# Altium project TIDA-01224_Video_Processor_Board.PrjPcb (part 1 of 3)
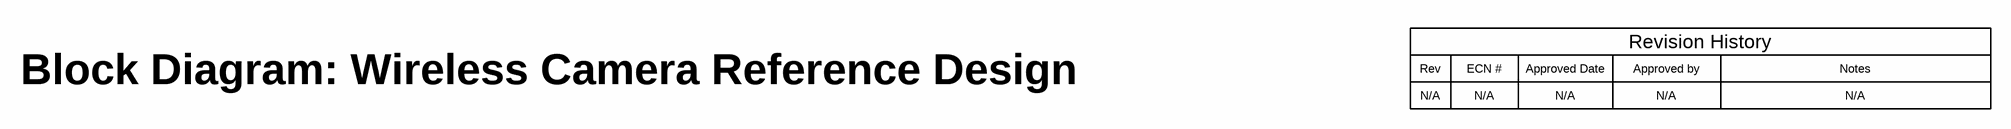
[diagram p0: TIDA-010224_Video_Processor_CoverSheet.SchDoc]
PRJ_Engineer: Sakshi Markhedkar; TID: TIDA-010224; TechSupport: http://www.ti.com/support; SCH_Rev: E1; PRJ_Title: Low-Power Wireless Camera Reference Design for Extended Battery Life; PRJ_Number: TIDA-010224; PRJ_Customer: Public Release; EVM_Orderable: N/A; Drawnby: Sakshi; CopyrightYear: 2018; Assembly Variant: 001
6 sheets, 509 parts. Net scope: global (net labels, ports and power ports of the same name join across sheets).
Board file: TIDA-010224_Video_Processor_PCB.PcbDoc
Sheets:
  TIDA-010224_Video_Processor_CoverSheet.SchDoc
  TIDA-010224_Video_Processor_Hardware.SchDoc
  TIDA-010224_Video_Processor_P01_Power_Delivery.SchDoc
  TIDA-010224_Video_Processor_P02_OA7000_Image_Sensor.SchDoc
  TIDA-010224_Video_Processor_P03_CC3235MODA_WIFI_Launchpad.SchDoc
  TIDA-010224_Video_Processor_P04_Peripherals.SchDoc

## Sheet TIDA-010224_Video_Processor_CoverSheet.SchDoc: TIDA-010224_Video_Processor_CoverSheet
size 431 x 279 mm; Date: Not shown in title block; ApprovedBy: Not shown in title block; CheckedBy: Not shown in title block; Author: Not shown in title block; CompanyName: Not shown in title block; DrawnBy: Sakshi Markhedkar; Engineer: Not shown in title block; Organization: Not shown in title block; Address1: Not shown in title block; Address2: Not shown in title block; Address3: Not shown in title block; Address4: Not shown in title block; DocumentNumber: 1; Revision: Use project parameter SCH_Rev; SheetNumber: 1; SheetTotal: 6; PageSetup: Record=PageOptions¦CenterHorizontal=True¦CenterVertical=True¦PrintScale=1.00¦XCorrection=1.00¦YCorrection=1.00¦PrintKind=0¦BorderSize=5000000¦LeftOffset=0¦BottomOffset=0¦Orientation=2¦PaperLength=1000¦PaperWidth=1000¦Scale=100¦PaperSource=15¦PrintQuality=600¦MediaType=1¦DitherType=10¦PaperKind=Letter¦PrintScaleMode=1

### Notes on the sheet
- Block Diagram: Wireless Camera Reference Design
- Rev
- N/A
- ECN #
- Approved Date
- Approved by
- Revision History
- Notes

## Sheet TIDA-010224_Video_Processor_Hardware.SchDoc: TIDA-010224_Hardware
size 431 x 279 mm; Date: Not shown in title block; ApprovedBy: Not shown in title block; CheckedBy: Not shown in title block; Author: Not shown in title block; CompanyName: Not shown in title block; DrawnBy: Sakshi Markhedkar; Engineer: Not shown in title block; Organization: Not shown in title block; Address1: Not shown in title block; Address2: Not shown in title block; Address3: Not shown in title block; Address4: Not shown in title block; DocumentNumber: 6; Revision: Use project parameter SCH_Rev; SheetNumber: 6; SheetTotal: 6; PageSetup: Record=PageOptions¦CenterHorizontal=True¦CenterVertical=True¦PrintScale=1.00¦XCorrection=1.00¦YCorrection=1.00¦PrintKind=0¦BorderSize=5000000¦LeftOffset=0¦BottomOffset=0¦Orientation=2¦PaperLength=1000¦PaperWidth=1000¦Scale=100¦PaperSource=15¦PrintQuality=600¦MediaType=1¦DitherType=10¦PaperKind=Letter¦PrintScaleMode=1
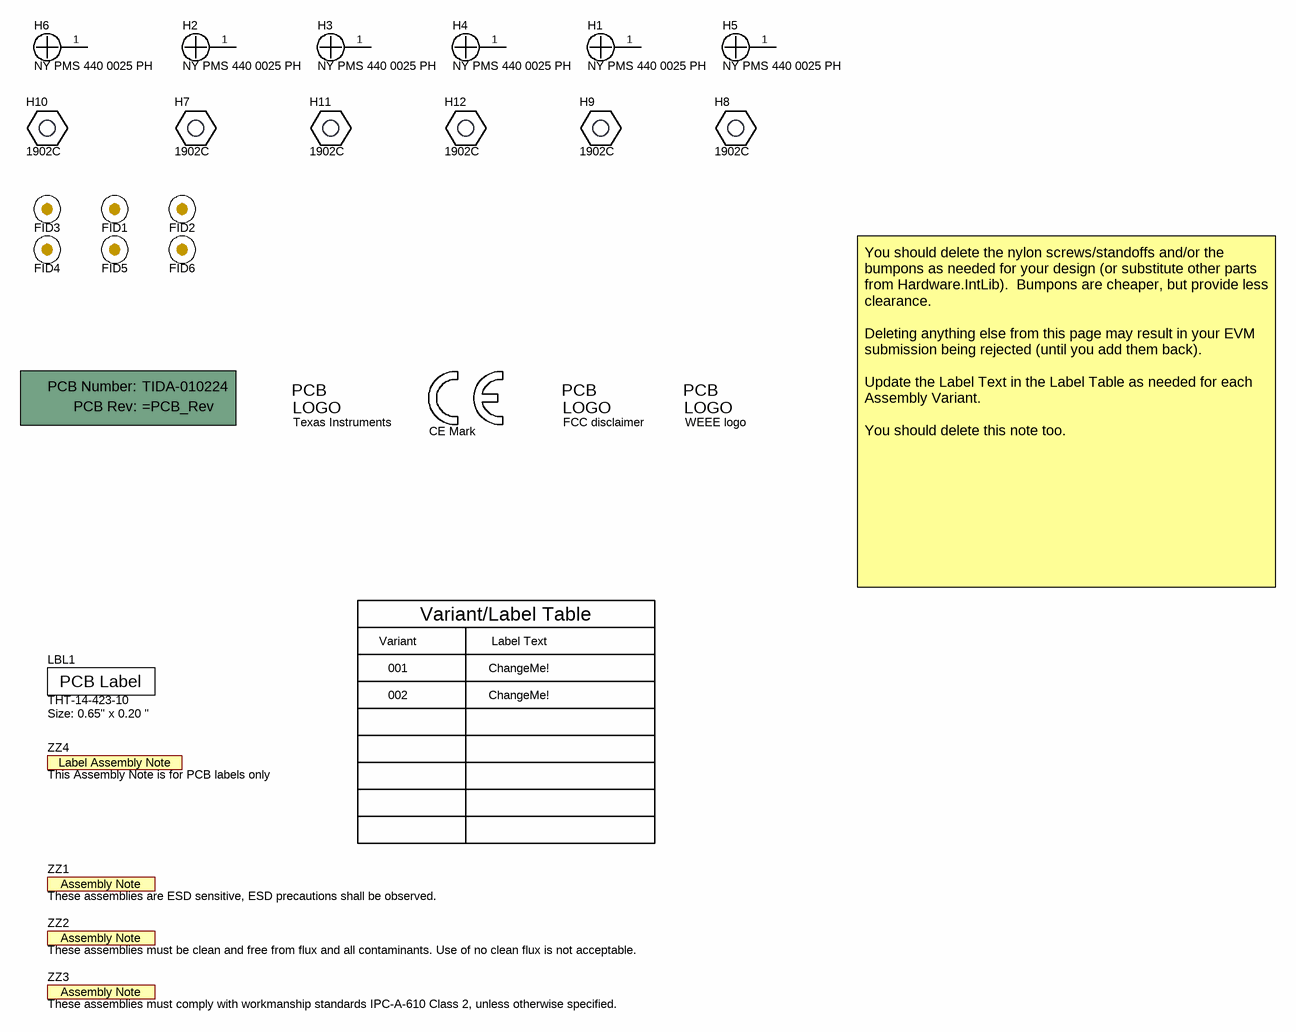
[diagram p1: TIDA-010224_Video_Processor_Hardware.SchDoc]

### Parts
!PCB1  Printed Circuit Board  (value not drawn)  (mechanical)
FID1  Fiducial  [Fiducial10-20]  (value not drawn)
FID2  Fiducial  [Fiducial10-20]  (value not drawn)
FID3  Fiducial  [Fiducial10-20]  (value not drawn)
FID4  Fiducial  [Fiducial10-20]  (value not drawn)
FID5  Fiducial  [Fiducial10-20]  (value not drawn)
FID6  Fiducial  [Fiducial10-20]  (value not drawn)
H1  NY PMS 440 0025 PH  [NY PMS 440 0025 PH]
H2  NY PMS 440 0025 PH  [NY PMS 440 0025 PH]
H3  NY PMS 440 0025 PH  [NY PMS 440 0025 PH]
H4  NY PMS 440 0025 PH  [NY PMS 440 0025 PH]
H5  NY PMS 440 0025 PH  [NY PMS 440 0025 PH]
H6  NY PMS 440 0025 PH  [NY PMS 440 0025 PH]
H7  1902C  [Keystone_1902C]
H8  1902C  [Keystone_1902C]
H9  1902C  [Keystone_1902C]
H10  1902C  [Keystone_1902C]
H11  1902C  [Keystone_1902C]
H12  1902C  [Keystone_1902C]
LBL1  THT-14-423-10  Note: Size: 0.65" x 0.20 "  [Label_650x200]
Logo1  FCC disclaimer  [FCC_disclaimer]  (no BOM)
Logo2  WEEE logo  [WEEE_Minimum]  (no BOM)
Logo3  Texas Instruments  [TI_Stacked_Overlay_Small]  (no BOM)
Logo4  CE Mark  [CE_Mark_5mm]  (no BOM)
ZZ1  These assemblies are ESD sensitive, ESD precautions shall be observed.  [AssemblyNote]  (no BOM)
ZZ2  These assemblies must be clean and free from flux and all contaminants. Use of no clean flux is not acceptable.  [AssemblyNote]  (no BOM)
ZZ3  These assemblies must comply with workmanship standards IPC-A-610 Class 2, unless otherwise specified.  [AssemblyNote]  (no BOM)
ZZ4  This Assembly Note is for PCB labels only  [AssemblyNoteLabel]  (no BOM)

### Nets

Not connected (* = marked no-connect by the designer): H1 1; H2 1; H3 1; H4 1; H5 1; H6 1

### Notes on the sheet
- Variant
- Variant/Label Table
- Label Text
- You should delete the nylon screws/standoffs and/or the bumpons as needed for your design (or substitute other parts from Hardware.IntLib).  Bumpons are cheaper, but provide less clearance.
  Deleting anything else from this page may result in your EVM submission being rejected (until you add them back).
  Update the Label Text in the Label Table as needed for each Assembly Variant.
  You should delete this note too.
- 001
- 002
- ChangeMe!

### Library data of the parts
!PCB1 = CMP-0003618-2: Manufacturer: Any; PartNumber: TIDA-010224
FID1-FID6 = CMP-0077181-1: Fiducial mark.  There is nothing to buy or mount.
H1-H6 = CMP-0003617-1: Machine Screw, Round, #4-40 x 1/4, Nylon, Philips panhead; Manufacturer: B&F Fastener Supply; CompType: Hardware
H7-H12 = CMP-0003610-1: Standoff, Hex, 0.5"L #4-40 Nylon; Manufacturer: Keystone; CompType: Hardware
LBL1 = CMP-0003625-1: Thermal Transfer Printable Labels, 0.650" W x 0.200" H - 10,000 per roll; Manufacturer: Brady; CompType: Label
Logo1 = CMP-0074847-1: FCC_disclaimer; Library Reference: Logo
Logo2 = CMP-0074769-1
Logo3 = CMP-0074838-1: Texas Instrument Corporate Signature; SymbolCreator: a0412235; Lib Reference: TI_Logo; Library Reference: Logo
Logo4 = CMP-0074844-1: SymbolCreator: a0412235
ZZ1 = CMP-0077236-1
ZZ2 = CMP-0077237-1
ZZ3 = CMP-0077238-1
ZZ4 = CMP-0003616-3

## Sheet TIDA-010224_Video_Processor_P01_Power_Delivery.SchDoc: TIDA-010224_P01_Peripherals
size A2; Date: Not shown in title block; ApprovedBy: Not shown in title block; CheckedBy: Not shown in title block; Author: Not shown in title block; CompanyName: Not shown in title block; DrawnBy: Sakshi Markhedkar; Engineer: Not shown in title block; Organization: Not shown in title block; Address1: Not shown in title block; Address2: Not shown in title block; Address3: Not shown in title block; Address4: Not shown in title block; DocumentNumber: 2; Revision: Use project parameter SCH_Rev; SheetNumber: 2; SheetTotal: 6; PageSetup: Record=PageOptions¦CenterHorizontal=True¦CenterVertical=True¦PrintScale=1.00¦XCorrection=1.00¦YCorrection=1.00¦PrintKind=0¦BorderSize=5000000¦LeftOffset=0¦BottomOffset=0¦Orientation=2¦PaperLength=1000¦PaperWidth=1000¦Scale=100¦PaperSource=15¦PrintQuality=600¦MediaType=1¦DitherType=10¦PaperKind=Letter¦PrintScaleMode=1
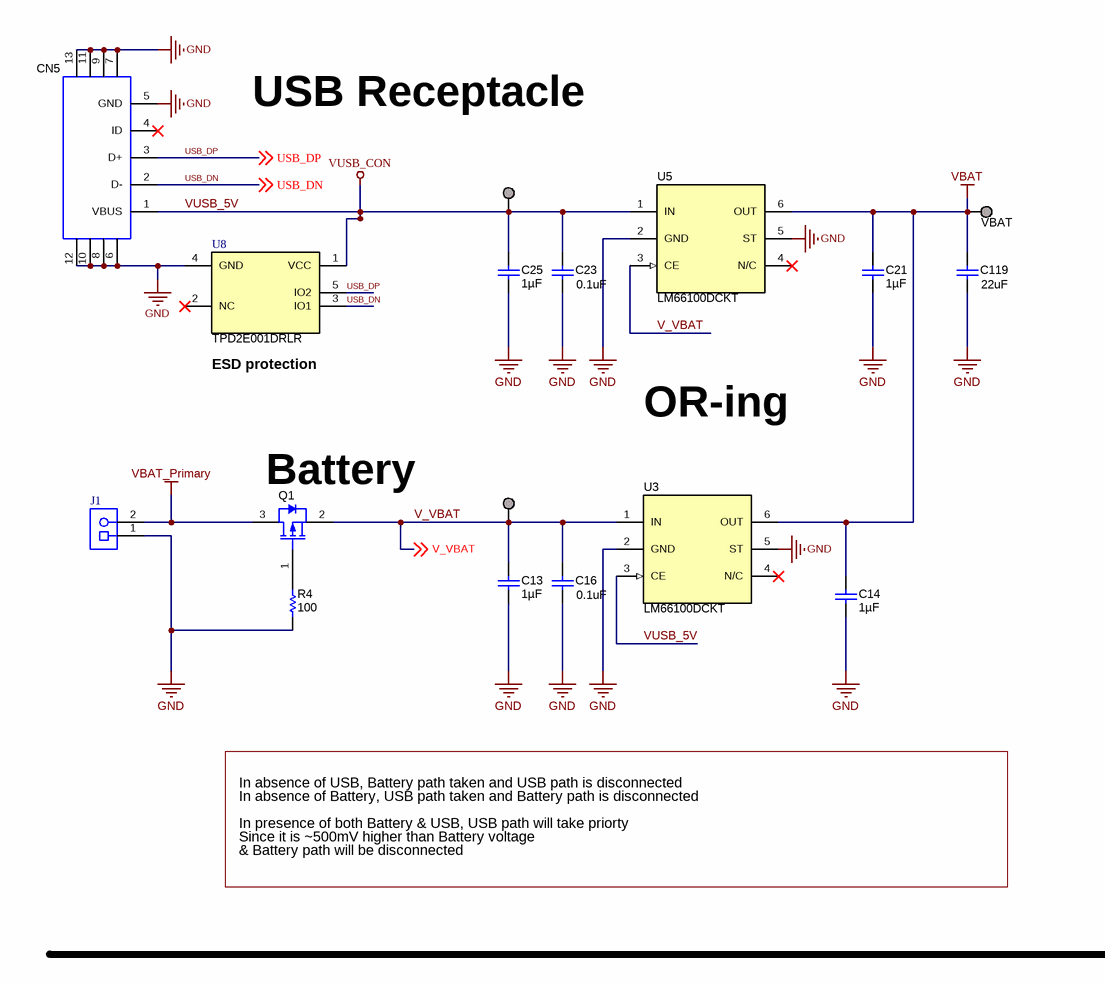
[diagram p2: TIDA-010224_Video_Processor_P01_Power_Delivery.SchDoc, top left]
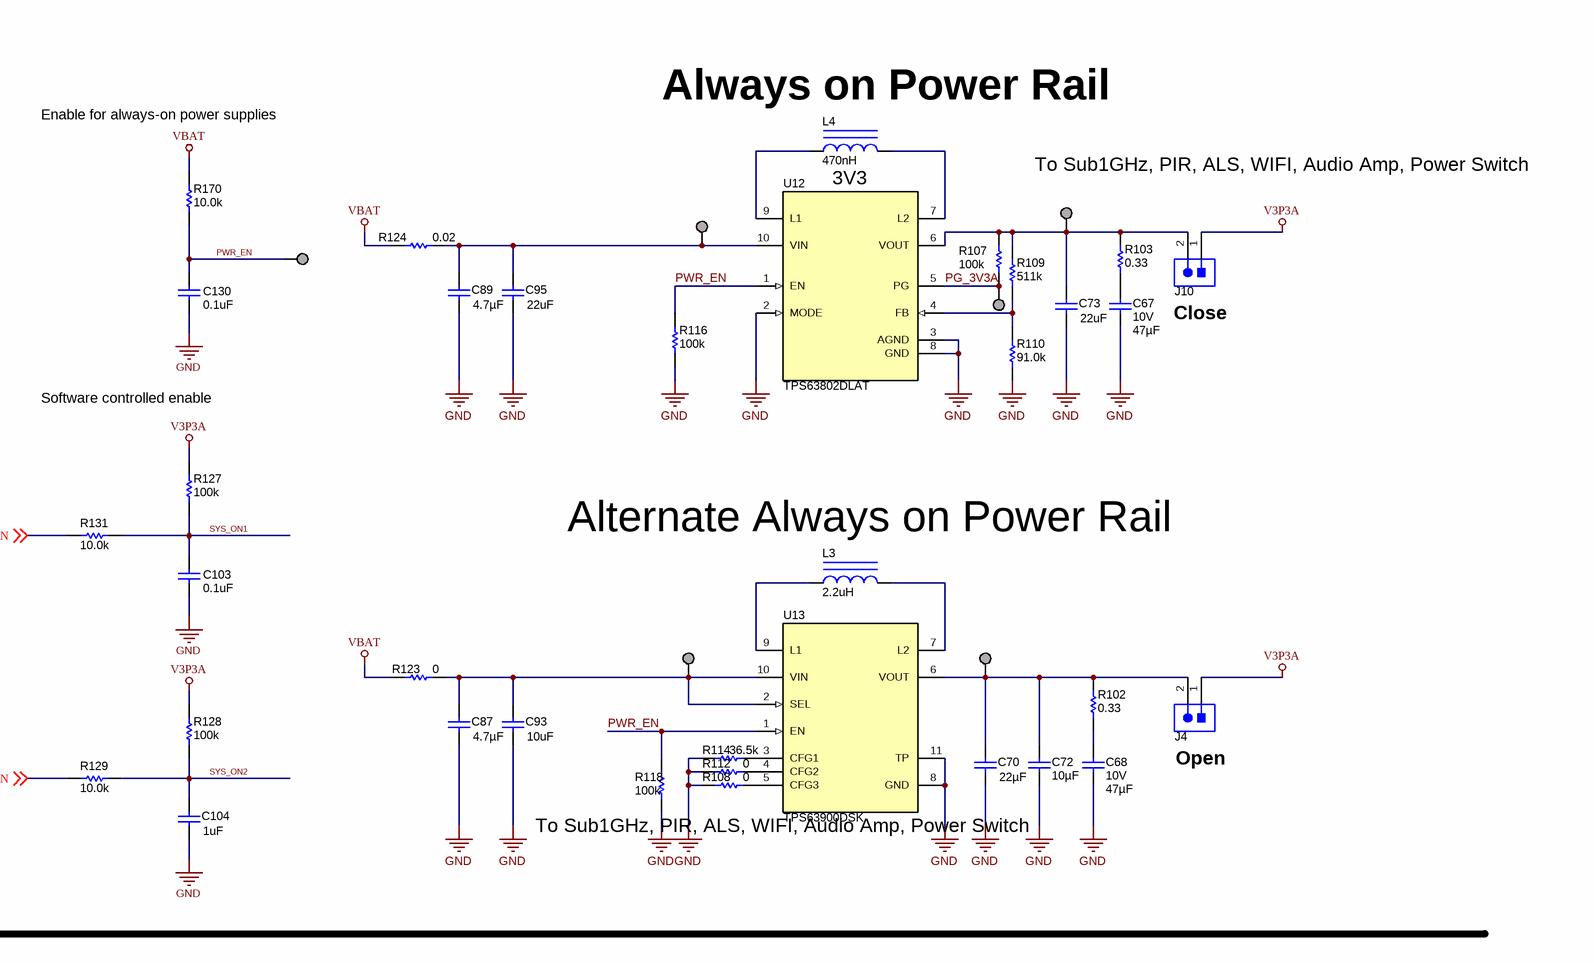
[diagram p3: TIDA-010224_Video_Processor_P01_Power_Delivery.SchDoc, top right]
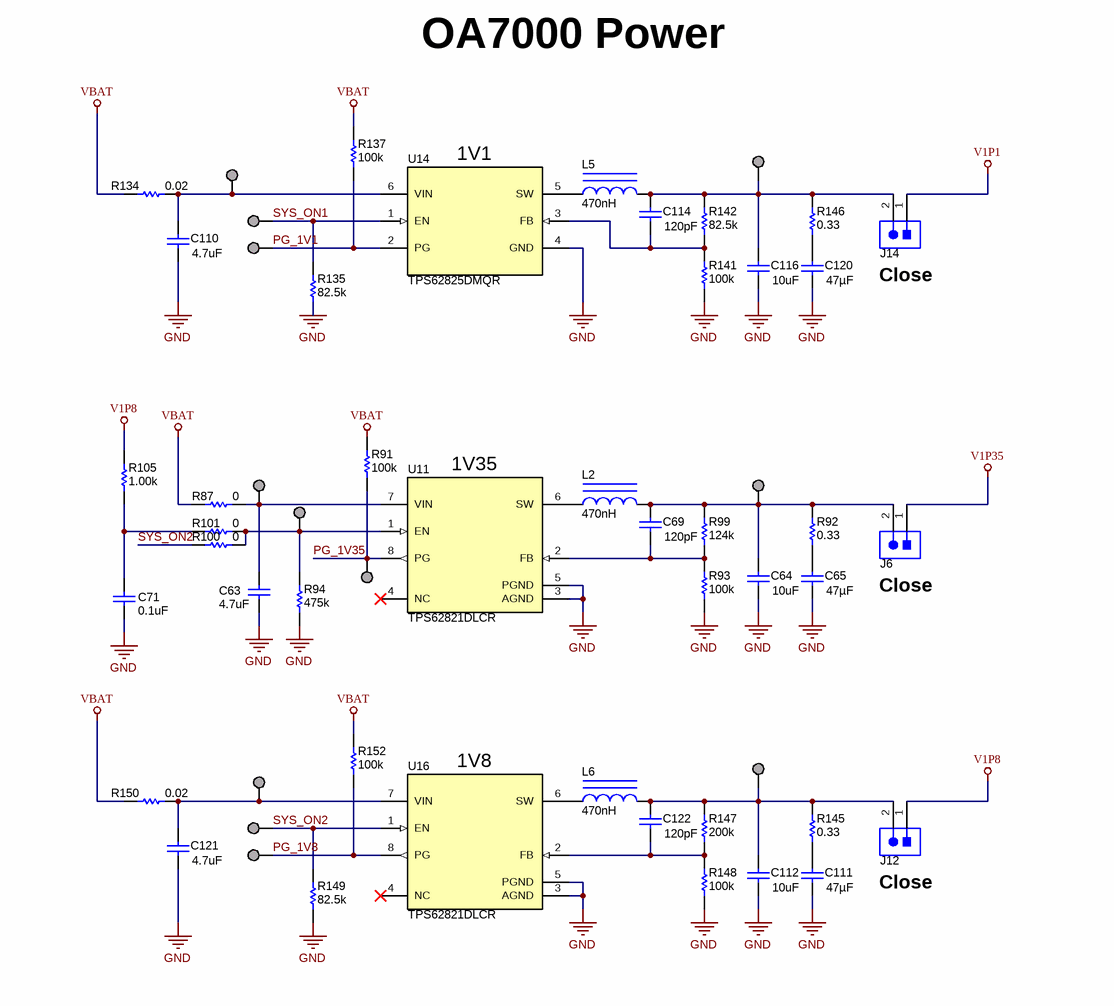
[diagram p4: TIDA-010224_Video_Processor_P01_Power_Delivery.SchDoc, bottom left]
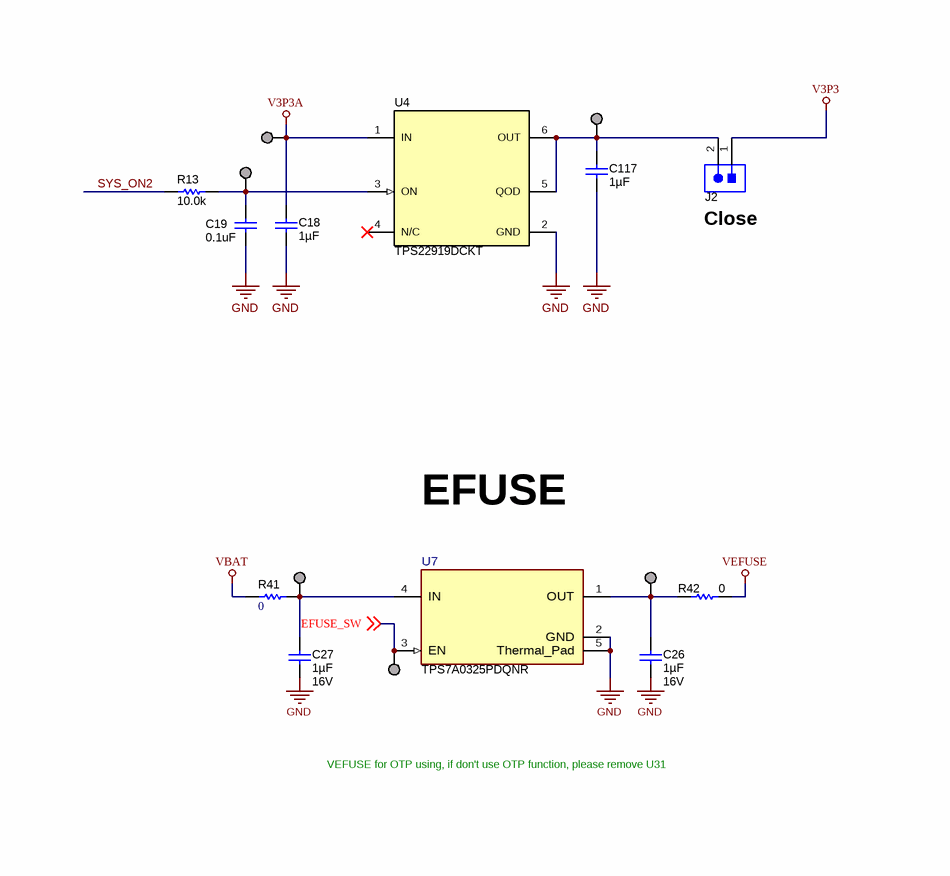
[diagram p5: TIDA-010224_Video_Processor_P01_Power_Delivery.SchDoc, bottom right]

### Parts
1.1V  TP_SM_1MM  [TP_SM_1MM]  (value not drawn)  (no BOM)
1.8V  TP_SM_1MM  [TP_SM_1MM]  (value not drawn)  (no BOM)
1.35V  TP_SM_1MM  [TP_SM_1MM]  (value not drawn)  (no BOM)
2.5V  TP_SM_1MM  [TP_SM_1MM]  (value not drawn)  (no BOM)
3.3V  TP_SM_1MM  [TP_SM_1MM]  (value not drawn)  (no BOM)
BAT  TP_SM_1MM  [TP_SM_1MM]  (value not drawn)  (no BOM)
C13  Cap_F: 1µF  [0603]  (hidden comment: GCM188R71C105MA64D)
C14  Cap_F: 1µF  [0603]  (hidden comment: GCM188R71C105MA64D)
C16  ValueDisplayed: 0.1uF  [0402]  (hidden comment: 885012205037)
C18  Cap_F: 1µF  [0603]  (hidden comment: GCM188R71C105MA64D)
C19  value 0.1uF  [0402]  (hidden comment: GRM155R71C104KA88D)
C21  Cap_F: 1µF  [0603]  (hidden comment: GCM188R71C105MA64D)
C23  ValueDisplayed: 0.1uF  [0402]  (hidden comment: 885012205037)
C25  Cap_F: 1µF  [0603]  (hidden comment: GCM188R71C105MA64D)
C26  Cap_F: 1µF  VDC_V: 16V  [0603]  (hidden comment: GCM188R71C105MA64D)
C27  Cap_F: 1µF  VDC_V: 16V  [0603]  (hidden comment: GCM188R71C105MA64D)
C63  ValueDisplayed: 4.7uF  [0603]  (hidden comment: C1608X7S1A475K080AC)
C64  ValueDisplayed: 10uF  [0805_HV]  (hidden comment: GRM21BR61E106KA73L)
C65  ValueDisplayed: 47µF  [0805_HV]  (hidden comment: GRM21BR61A476ME15L)
C67  VDC_V: 10V  ValueDisplayed: 47µF  [0805_HV]  (hidden comment: GRM21BR61A476ME15L)
C68  VDC_V: 10V  ValueDisplayed: 47µF  [0805_HV]  (hidden comment: GRM21BR61A476ME15L)
C69  ValueDisplayed: 120pF  [0402]  (hidden comment: GRM1555C1H121JA01D)
C70  ValueDisplayed: 22µF  [0603]  (hidden comment: CL10A226MO7JZNC)
C71  value 0.1uF  [0402]  (hidden comment: GRM155R71C104KA88D)
C72  Cap_F: 10µF  [0805_HV]  (hidden comment: CL21B106KOQNNNE)
C73  ValueDisplayed: 22uF  [0603]  (hidden comment: C1608X5R1A226M080AC)
C87  ValueDisplayed: 4.7µF  [0402_065]  (hidden comment: CC0402MRX5R7BB475)
C89  ValueDisplayed: 4.7µF  [0402_065]  (hidden comment: CC0402MRX5R7BB475)
C93  ValueDisplayed: 10uF  [0603]  (hidden comment: GRM188R60J106ME47D)
C95  ValueDisplayed: 22uF  [0603]  (hidden comment: GRM188R60J226MEA0D)
C103  value 0.1uF  [0402]  (hidden comment: GRM155R71C104KA88D)
C104  ValueDisplayed: 1uF  [0402]  (hidden comment: GRM155R70J105MA12D)
C110  ValueDisplayed: 4.7uF  [0603]  (hidden comment: C1608X7S1A475K080AC)
C111  ValueDisplayed: 47µF  [0805_HV]  (hidden comment: GRM21BR61A476ME15L)
C112  ValueDisplayed: 10uF  [0603]  (hidden comment: GRM188R60G106ME47D)
C114  ValueDisplayed: 120pF  [0402]  (hidden comment: GRM1555C1H121JA01D)
C116  ValueDisplayed: 10uF  [0402_070]  (hidden comment: GRM155R60G106ME44D)
C117  Cap_F: 1µF  [0603]  (hidden comment: GCM188R71C105MA64D)
C119  ValueDisplayed: 22uF  [1210_280]  (hidden comment: CGA6P1X7R1C226M250AC)
C120  ValueDisplayed: 47µF  [0805_HV]  (hidden comment: GRM21BR61A476ME15L)
C121  ValueDisplayed: 4.7uF  [0603]  (hidden comment: C1608X7S1A475K080AC)
C122  ValueDisplayed: 120pF  [0402]  (hidden comment: GRM1555C1H121JA01D)
C130  value 0.1uF  [0402]  (hidden comment: GRM155R71C104KA88D)
CN5  ZX62R-B-5P(30)  [Hirose_ZX62R-B-5P]  (value not drawn)
EN  TP_SM_1MM  [TP_SM_1MM]  (value not drawn)  (no BOM)
EN_1.35V  TP_SM_1MM  [TP_SM_1MM]  (value not drawn)  (no BOM)
IN1  TP_SM_1MM  [TP_SM_1MM]  (value not drawn)  (no BOM)
IN2  TP_SM_1MM  [TP_SM_1MM]  (value not drawn)  (no BOM)
IN_1.1V  TP_SM_1MM  [TP_SM_1MM]  (value not drawn)  (no BOM)
IN_1.8V  TP_SM_1MM  [TP_SM_1MM]  (value not drawn)  (no BOM)
IN_1.35V  TP_SM_1MM  [TP_SM_1MM]  (value not drawn)  (no BOM)
IN_2.5V  TP_SM_1MM  [TP_SM_1MM]  (value not drawn)  (no BOM)
IN_3.3V  TP_SM_1MM  [TP_SM_1MM]  (value not drawn)  (no BOM)
J1  1715721  [PhoenixContact_1715721]  (value not drawn)
J2  M22-2510205  [Harwin_M22-2510205]  (value not drawn)
J4  M22-2510205  [Harwin_M22-2510205]  (value not drawn)
J6  M22-2510205  [Harwin_M22-2510205]  (value not drawn)
J10  M22-2510205  [Harwin_M22-2510205]  (value not drawn)
J12  M22-2510205  [Harwin_M22-2510205]  (value not drawn)
J14  M22-2510205  [Harwin_M22-2510205]  (value not drawn)
L2  ValueDisplayed: 470nH  [DFE201610E]  (hidden comment: DFE201610E-R47M=P2)
L3  ValueDisplayed: 2.2uH  [XFL4020]  (hidden comment: XFL4020-222MEB)
L4  ValueDisplayed: 470nH  [DFE201610E]  (hidden comment: DFE201610E-R47M=P2)
L5  ValueDisplayed: 470nH  [DFE201610E]  (hidden comment: DFE201610E-R47M=P2)
L6  ValueDisplayed: 470nH  [DFE201610E]  (hidden comment: DFE201610E-R47M=P2)
ON  TP_SM_1MM  [TP_SM_1MM]  (value not drawn)  (no BOM)
PG_1.1V  TP_SM_1MM  [TP_SM_1MM]  (value not drawn)  (no BOM)
PG_1.8V  TP_SM_1MM  [TP_SM_1MM]  (value not drawn)  (no BOM)
PG_1.35V  TP_SM_1MM  [TP_SM_1MM]  (value not drawn)  (no BOM)
PG_3.3V  TP_SM_1MM  [TP_SM_1MM]  (value not drawn)  (no BOM)
PWR_EN  TP_SM_1MM  [TP_SM_1MM]  (value not drawn)  (no BOM)
Q1  SI2323DS  [SOT-23]  (value not drawn)
R4  ValueDisplayed: 100  [0402]  (hidden comment: ERJ-2GEJ101X)
R13  ValueDisplayed: 10.0k  [0402]  (hidden comment: ERJPA2F1002X)
R41  ValueDisplayed: 0  [0402]  (hidden comment: Resistor)
R42  ValueDisplayed: 0  [0603]  (hidden comment: RMCF0603ZT0R00)
R87  ValueDisplayed: 0  [0603]  (hidden comment: RMCF0603ZT0R00)
R91  ValueDisplayed: 100k  [0805_HV]  (hidden comment: RR1220P-104-D)
R92  ValueDisplayed: 0.33  [0402]  (hidden comment: ERJ-2BQFR33X)
R93  ValueDisplayed: 100k  [0402]  (hidden comment: CRCW0402100KFKED)
R94  ValueDisplayed: 475k  [0402]  (hidden comment: CRCW0402475KFKED)
R99  ValueDisplayed: 124k  [0402]  (hidden comment: CRCW0402124KFKED)
R100  ValueDisplayed: 0  [0603]  (hidden comment: RMCF0603ZT0R00)
R101  ValueDisplayed: 0  [0603]  (hidden comment: RMCF0603ZT0R00)
R102  ValueDisplayed: 0.33  [0402]  (hidden comment: ERJ-2BQFR33X)
R103  ValueDisplayed: 0.33  [0402]  (hidden comment: ERJ-2BQFR33X)
R105  ValueDisplayed: 1.00k  [0402]  (hidden comment: CRCW04021K00FKED)
R107  ValueDisplayed: 100k  [0402]  (hidden comment: CRCW0402100KFKED)
R108  ValueDisplayed: 0  [0603]  (hidden comment: RMCF0603ZT0R00)
R109  ValueDisplayed: 511k  [0201]  (hidden comment: RC0201FR-07511KL)
R110  ValueDisplayed: 91.0k  [0603]  (hidden comment: RC0603FR-0791KL)
R112  ValueDisplayed: 0  [0603]  (hidden comment: RMCF0603ZT0R00)
R114  ValueDisplayed: 36.5k  [0603]  (hidden comment: CRCW060336K5FKEA)
R116  ValueDisplayed: 100k  [0201]  (hidden comment: RC0201FR-07100KL)
R118  ValueDisplayed: 100k  [0201]  (hidden comment: RC0201FR-07100KL)
R123  ValueDisplayed: 0  [0603]  (hidden comment: RMCF0603ZT0R00)
R124  ValueDisplayed: 0.02  [0603]  (hidden comment: RL0603FR-070R02L)
R127  ValueDisplayed: 100k  [0402]  (hidden comment: RG1005P-104-B-T5)
R128  ValueDisplayed: 100k  [0402]  (hidden comment: RG1005P-104-B-T5)
R129  ValueDisplayed: 10.0k  [0402]  (hidden comment: ERJPA2F1002X)
R131  ValueDisplayed: 10.0k  [0402]  (hidden comment: ERJPA2F1002X)
R134  ValueDisplayed: 0.02  [0603]  (hidden comment: RL0603FR-070R02L)
R135  ValueDisplayed: 82.5k  [0201]  (hidden comment: RC0201FR-0782K5L)
R137  ValueDisplayed: 100k  [0805_HV]  (hidden comment: RR1220P-104-D)
R141  ValueDisplayed: 100k  [0402]  (hidden comment: CRCW0402100KFKED)
R142  ValueDisplayed: 82.5k  [0402]  (hidden comment: CRCW040282K5FKED)
R145  ValueDisplayed: 0.33  [0402]  (hidden comment: ERJ-2BQFR33X)
R146  ValueDisplayed: 0.33  [0402]  (hidden comment: ERJ-2BQFR33X)
R147  ValueDisplayed: 200k  [0402]  (hidden comment: CRCW0402200KFKED)
R148  ValueDisplayed: 100k  [0402]  (hidden comment: CRCW0402100KFKED)
R149  ValueDisplayed: 82.5k  [0201]  (hidden comment: RC0201FR-0782K5L)
R150  ValueDisplayed: 0.02  [0603]  (hidden comment: RL0603FR-070R02L)
R152  ValueDisplayed: 100k  [0805_HV]  (hidden comment: RR1220P-104-D)
R170  ValueDisplayed: 10.0k  [0402]  (hidden comment: ERJPA2F1002X)
SYSON1  TP_SM_1MM  [TP_SM_1MM]  (value not drawn)  (no BOM)
SYSON2  TP_SM_1MM  [TP_SM_1MM]  (value not drawn)  (no BOM)
U3  LM66100DCKT  [DCK0006A_N]
U4  TPS22919DCKT  [DCK0006A_N]
U5  LM66100DCKT  [DCK0006A_N]
U7  TPS7A0325PDQNR  [DQN0004A-MFG]
U8  TPD2E001DRLR  [DRL0005A]
U11  TPS62821DLCR  [DLC0008A]
U12  TPS63802DLAT  [DLA0010A]
U13  TPS63900DSK  [DSK0010A]
U14  TPS62825DMQR  [DMQ0006A]
U16  TPS62821DLCR  [DLC0008A]
USB  TP_SM_1MM  [TP_SM_1MM]  (value not drawn)  (no BOM)
VBAT  RCU-0C  [TE_RCU]  (value not drawn)
VOUT1  TP_SM_1MM  [TP_SM_1MM]  (value not drawn)  (no BOM)
VOUT2  TP_SM_1MM  [TP_SM_1MM]  (value not drawn)  (no BOM)

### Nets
GND: C13.2 C14.2 C16.2 C18.2 C19.1 C21.2 C23.2 C25.2 C26.2 C27.2 C63.2 C64.2 C65.2 C67.2 C68.2 C70.2 C71.1 C72.2 C73.2 C87.2 C89.2 C93.2 C95.2 C103.1 C104.2 C110.2 C111.2 C112.2 C116.2 C117.2 C119.2 C120.2 C121.2 C130.1 CN5.5(GND) CN5.6 CN5.7 CN5.8 CN5.9 CN5.10 CN5.11 CN5.12 CN5.13 J1.1 R4.1 R93.1 R94.1 R108.1 R110.1 R112.1 R114.1 R116.2 R118.2 R135.2 R141.1 R148.1 R149.2 U3.2(GND) U3.5(ST) U4.2(GND) U5.2(GND) U5.5(ST) U7.2(GND) U7.5(Thermal_Pad) U8.4(GND) U11.3(AGND) U11.5(PGND) U12.2(MODE) U12.3(AGND) U12.8(GND) U13.8(GND) U13.11(TP) U14.4(GND) U16.3(AGND) U16.5(PGND)
V1P1: J14.1
V1P8: J12.1 R105.2
V1P35: J6.1
V3P3: J2.1
V3P3A: C18.1 IN_3.3V.1 J4.1 J10.1 R127.2 R128.2 U4.1(IN)
VBAT: C14.1 C21.1 C119.1 R41.2 R87.1 R91.2 R123.1 R124.1 R134.1 R137.2 R150.1 R152.2 R170.2 U3.6(OUT) U5.6(OUT) VBAT.1
VBAT_Primary: J1.2 Q1.3(D)
VEFUSE: R42.2
VUSB_5V: C23.1 C25.1 CN5.1(VBUS) U3.3(CE) U5.1(IN) U8.1(VCC) USB.1  [also labelled VUSB_CON]
EFUSE_SW: EN.1 U7.3(EN) ; off-sheet EFUSE_SW
HOST_ON: R129.2 R131.2 ; off-sheet HOST_ON
PG_1V1: PG_1.1V.1 R137.1 U14.2(PG)
PG_1V8: PG_1.8V.1 R152.1 U16.8(PG)
PG_1V35: PG_1.35V.1 R91.1 U11.8(PG)
PG_3V3A: PG_3.3V.1 R107.1 U12.5(PG)
PWR_EN: C130.2 PWR_EN.1 R116.1 R118.1 R170.1 U12.1(EN) U13.1(EN)
SYS_ON1: C103.2 R127.1 R131.1 R135.1 SYSON1.1 U14.1(EN)
SYS_ON2: C104.1 R13.1 R100.1 R128.1 R129.1 R149.1 SYSON2.1 U16.1(EN)
USB_DN: CN5.2(D-) U8.3(IO1) ; off-sheet USB_DN
USB_DP: CN5.3(D+) U8.5(IO2) ; off-sheet USB_DP
V_VBAT: BAT.1 C13.1 C16.1 Q1.2(S) U3.1(IN) U5.3(CE) ; off-sheet V_VBAT
Net1.1V_1: 1.1V.1 C114.1 C116.1 J14.2 L5.2 R142.2 R146.2
Net1.8V_1: 1.8V.1 C112.1 C122.1 J12.2 L6.2 R145.2 R147.2
Net1.35V_1: 1.35V.1 C64.1 C69.1 J6.2 L2.2 R92.2 R99.2
Net2.5V_1: 2.5V.1 C26.1 R42.1 U7.1(OUT)
Net3.3V_1: 3.3V.1 C117.1 J2.2 U4.5(QOD) U4.6(OUT)
NetC19_2: C19.2 ON.1 R13.2 U4.3(ON)
NetC27_1: C27.1 IN_2.5V.1 R41.1 U7.4(IN)
NetC63_1: C63.1 IN_1.35V.1 R87.2 U11.7(VIN)
NetC65_1: C65.1 R92.1
NetC67_1: C67.1 R103.1
NetC68_1: C68.1 R102.1
NetC69_2: C69.2 R93.2 R99.1 U11.2(FB)
NetC70_1: C70.1 C72.1 J4.2 R102.2 U13.6(VOUT) VOUT2.1
NetC71_2: C71.2 R101.1 R105.1
NetC73_1: C73.1 J10.2 R103.2 R107.2 R109.2 U12.6(VOUT) VOUT1.1
NetC87_1: C87.1 C93.1 IN2.1 R123.2 U13.2(SEL) U13.10(VIN)
NetC89_1: C89.1 C95.1 IN1.1 R124.2 U12.10(VIN)
NetC110_1: C110.1 IN_1.1V.1 R134.2 U14.6(VIN)
NetC111_1: C111.1 R145.1
NetC114_2: C114.2 R141.2 R142.1 U14.3(FB)
NetC120_1: C120.1 R146.1
NetC121_1: C121.1 IN_1.8V.1 R150.2 U16.7(VIN)
NetC122_2: C122.2 R147.1 R148.2 U16.2(FB)
NetEN_1.35V_1: EN_1.35V.1 R94.2 R100.2 R101.2 U11.1(EN)
NetL2_1: L2.1 U11.6(SW)
NetL3_1: L3.1 U13.9(L1)
NetL3_2: L3.2 U13.7(L2)
NetL4_1: L4.1 U12.9(L1)
NetL4_2: L4.2 U12.7(L2)
NetL5_1: L5.1 U14.5(SW)
NetL6_1: L6.1 U16.6(SW)
NetQ1_1: Q1.1(G) R4.2
NetR108_2: R108.2 U13.5(CFG3)
NetR109_1: R109.1 R110.2 U12.4(FB)
NetR112_2: R112.2 U13.4(CFG2)
NetR114_2: R114.2 U13.3(CFG1)

Not connected (* = marked no-connect by the designer): CN5 4(ID)*; U3 4(N/C)*; U4 4(N/C)*; U5 4(N/C)*; U8 2(NC)*; U11 4(NC)*; U16 4(NC)*

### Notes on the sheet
- USB Receptacle
- Enable for always-on power supplies
- (near L4) Always on Power Rail
- (near L4) 3V3
- (near VOUT1) To Sub1GHz, PIR, ALS, WIFI, Audio Amp, Power Switch
- (near U8) ESD protection
- Close
- OR-ing
- Software controlled enable
- (near Q1) Battery
- (near L3) Alternate Always on Power Rail
- (near J4) Open
- In absence of USB, Battery path taken and USB path is disconnected
- In absence of Battery, USB path taken and Battery path is disconnected
- In presence of both Battery & USB, USB path will take priorty
- Since it is ~500mV higher than Battery voltage
- (near R118) To Sub1GHz, PIR, ALS, WIFI, Audio Amp, Power Switch
- & Battery path will be disconnected
- OA7000 Power
- (near U14) 1V1
- (near J14) Close
- (near J2) Close
- (near U11) 1V35
- (near J6) Close
- EFUSE
- (near U16) 1V8
- (near J12) Close
- VEFUSE for OTP using, if don't use OTP function, please remove U31

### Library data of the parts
1.1V 1.8V 1.35V 2.5V 3.3V BAT EN EN_1.35V IN1 IN2 IN_1.1V IN_1.8V IN_1.35V IN_2.5V IN_3.3V ON PG_1.1V PG_1.8V PG_1.35V PG_3.3V PWR_EN SYSON1 SYSON2 USB VOUT1 VOUT2 = CMP-0003825-1: 1mm Test Point, SMT; Manufacturer: Any
C13 C14 C18 C21 C25 C117 = CMP-0007137-1: CAP, CERM, 1 uF, 16 V, +/- 20%, X7R, AEC-Q200 Grade 1, 0603; Manufacturer: MuRata; TaMin_C: -55°C; Polarized: N; SizeAreaWB_mm2: 4.68; Value1: Unknown; U/M: EA; Value: 1uF; TaMax_C: 125°C; SizeZ_mm: 1; SizeX_mm: 1.6; SizeY_mm: 0.8; Value2: 16V; SizeArea_mm2: 1.28; AEC Qualified: Y; AEC Category: Q200
C16 C23 = CMP-0006228-1: CAP, CERM, 0.1 uF, 16 V, +/- 10%, X7R, 0402; Manufacturer: Wurth Elektronik; TaMin_C: -55°C; Polarized: N; SizeAreaWB_mm2: 3; Value1: Unknown; U/M: EA; Value: 0.1uF; TaMax_C: 125°C; SizeZ_mm: 0.6; SizeX_mm: 1; SizeY_mm: 0.5; Value2: 16V; Cap_F: 100nF; AEC Category: Q200
C19 C71 C103 C130 = Cap: CAP CER 0.1UF 16V 10% X7R 0402; Manufacturer: Murata Electronics North America
C26 C27 = CMP-0007137-1: CAP, CERM, 1 uF, 16 V, +/- 20%, X7R, AEC-Q200 Grade 1, 0603; Manufacturer: MuRata; TaMin_C: -55°C; Polarized: N; SizeAreaWB_mm2: 4.68; Value1: Unknown; U/M: EA; Value: 1uF; TaMax_C: 125°C; SizeZ_mm: 1; SizeX_mm: 1.6; SizeY_mm: 0.8; SizeArea_mm2: 1.28; AEC Qualified: Y; AEC Category: Q200
C63 C110 C121 = CMP-0007058-4: CAP, CERM, 4.7 uF, 10 V, +/- 10%, X7S, 0603; Manufacturer: TDK; TaMin_C: -55°C; Polarized: N; SizeAreaWB_mm2: 4.68; Value1: Unknown; U/M: EA; Value: 4.7uF; TaMax_C: 125°C; SizeZ_mm: 1; SizeX_mm: 1.6; SizeY_mm: 0.8; Value2: 10V; SizeArea_mm2: 1.28; Cap_F: 4.7µF; AEC Category: Q200
C64 = CMP-0008302-2: CAP, CERM, 10 uF, 25 V, +/- 10%, X5R, 0805; Manufacturer: MuRata; TaMin_C: -55°C; Polarized: N; SizeAreaWB_mm2: 6.75; Value1: Unknown; U/M: EA; Value: 10uF; TaMax_C: 85°C; SizeZ_mm: 1.45; SizeX_mm: 2; SizeY_mm: 1.25; Cap_Case: 0805; Value2: 25V; SizeArea_mm2: 2.5; Cap_F: 10µF; AEC Category: Q200
C65 C111 C120 = CMP-0078699-1: CAP, CERM, 47 µF, 10 V,+/- 20%, X5R, 0805; Manufacturer: MuRata; TaMin_C: -55°C; Polarized: N; Green_Lifecycle: Active; SizeAreaWB_mm2: 6.75; Green_REACh: Passed; U/M: EA; Value: 47uF; TaMax_C: 85°C; SizeZ_mm: 1.45; SizeX_mm: 2; SizeY_mm: 1.25; Cap_Case: 0805; Value2: 10V; SizeArea_mm2: 2.5; AEC Category: Q200
C67 C68 = CMP-0078699-1: CAP, CERM, 47 µF, 10 V,+/- 20%, X5R, 0805; Manufacturer: MuRata; TaMin_C: -55°C; Polarized: N; Green_Lifecycle: Active; SizeAreaWB_mm2: 6.75; Green_REACh: Passed; U/M: EA; Value: 47uF; TaMax_C: 85°C; SizeZ_mm: 1.45; SizeX_mm: 2; SizeY_mm: 1.25; Cap_Case: 0805; SizeArea_mm2: 2.5; AEC Category: Q200
C69 C114 C122 = CMP-0006417-2: CAP, CERM, 120 pF, 50 V, +/- 5%, C0G/NP0, 0402; Manufacturer: MuRata; TaMin_C: -55°C; Polarized: N; SizeAreaWB_mm2: 3; Value1: Unknown; U/M: EA; Value: 120pF; TaMax_C: 125°C; SizeZ_mm: 0.6; SizeX_mm: 1; SizeY_mm: 0.5; Value2: 50V; AEC Category: Q200
C70 = CMP-0081159-1: CAP, CERM, 22 µF, 16 V,+/- 20%, X5R, 0603; Manufacturer: Samsung; SizeAreaWB_mm2: 4.68; SizeArea_mm2: 1.28; AEC Qualified: N; AEC Category: Q200; Value: 22uF; TaMax_C: 85°C; SizeZ_mm: 1; TaMin_C: -55°C; VDC_V: 16V; SizeY_mm: 0.8; U/M: EA; SizeX_mm: 1.6
C72 = CMP-0007995-1: CAP, CERM, 10 uF, 16 V, +/- 10%, X7R, 0805; Manufacturer: Samsung Electro-Mechanics; TaMin_C: -55°C; Polarized: N; SizeAreaWB_mm2: 6.75; Value1: Unknown; U/M: EA; Value: 10uF; TaMax_C: 125°C; SizeZ_mm: 1.45; SizeX_mm: 2; SizeY_mm: 1.25; Cap_Case: 0805; Value2: 16V; SizeArea_mm2: 2.5; AEC Category: Q200
C73 = CMP-0007005-5: CAP, CERM, 22 uF, 10 V, +/- 20%, X5R, 0603; Manufacturer: TDK; TaMin_C: -55°C; ESR_ohm: 3.71m; Polarized: N; SizeAreaWB_mm2: 4.68; Value1: 0.00371 ohm; U/M: EA; Value: 22uF; TaMax_C: 85°C; SizeZ_mm: 1; SizeX_mm: 1.6; SizeY_mm: 0.8; Value2: 10V; SizeArea_mm2: 1.28; Cap_F: 22µF; IRMS_A: 2.69936A; AEC Category: Q200
C87 C89 = CMP-0078507-1: CAP, CERM, 4.7 µF, 16 V,+/- 20%, X5R, 0402; Manufacturer: Yageo America; SizeAreaWB_mm2: 3; SizeArea_mm2: 0.5; AEC Qualified: N; AEC Category: Q200; Value: 4.7uF; TaMax_C: 85°C; SizeZ_mm: 0.65; TaMin_C: -55°C; VDC_V: 16V; U/M: EA; SizeX_mm: 1; Cap_Case: 0402
C93 = CMP-0007303-5: CAP, CERM, 10 uF, 6.3 V, +/- 20%, X5R, 0603; Manufacturer: MuRata; TaMin_C: -55°C; ESR_ohm: 9m; Polarized: N; SizeAreaWB_mm2: 4.68; Value1: 0.009 ohm; U/M: EA; Value: 10uF; TaMax_C: 125°C; SizeZ_mm: 1; SizeX_mm: 1.6; SizeY_mm: 0.8; Value2: 6.3V; SizeArea_mm2: 1.28; Cap_F: 10µF; IRMS_A: 2.74A; AEC Category: Q200
C95 = CMP-0007306-5: CAP, CERM, 22 uF, 6.3 V, +/- 20%, X5R, 0603; Manufacturer: MuRata; TaMin_C: -55°C; Polarized: N; SizeAreaWB_mm2: 4.68; Value1: Unknown; U/M: EA; Value: 22uF; TaMax_C: 85°C; SizeZ_mm: 1; SizeX_mm: 1.6; SizeY_mm: 0.8; Value2: 6.3V; SizeArea_mm2: 1.28; Cap_F: 22µF; AEC Category: Q200
C104 = CMP-0006624-1: CAP, CERM, 1 uF, 6.3 V, +/- 20%, X7R, 0402; Manufacturer: MuRata; TaMin_C: -55°C; Polarized: N; SizeAreaWB_mm2: 3; Value1: Unknown; U/M: EA; Value: 1uF; TaMax_C: 125°C; SizeZ_mm: 0.6; SizeX_mm: 1; SizeY_mm: 0.5; Value2: 6.3V; Cap_F: 1µF; AEC Category: Q200
C112 = CMP-0007299-5: CAP, CERM, 10 uF, 4 V, +/- 20%, X5R, 0603; Manufacturer: MuRata; TaMin_C: -55°C; ESR_ohm: 3m; Polarized: N; SizeAreaWB_mm2: 4.68; Value1: 0.003 ohm; U/M: EA; Value: 10uF; TaMax_C: 85°C; SizeZ_mm: 1; SizeX_mm: 1.6; SizeY_mm: 0.8; Value2: 4V; SizeArea_mm2: 1.28; Cap_F: 10µF; IRMS_A: 3A; AEC Category: Q200
C116 = CMP-0006528-2: CAP, CERM, 10 uF, 4 V, +/- 20%, X5R, 0402; Manufacturer: MuRata; TaMin_C: -55°C; Polarized: N; SizeAreaWB_mm2: 3; Value1: Unknown; U/M: EA; Value: 10uF; TaMax_C: 85°C; SizeZ_mm: 0.7; SizeX_mm: 1; SizeY_mm: 0.5; Cap_Case: 0402; Value2: 4V; Cap_F: 10µF; AEC Category: Q200
C119 = CMP-0009154-2: CAP, CERM, 22 uF, 16 V, +/- 20%, X7R, AEC-Q200 Grade 1, 1210; Manufacturer: TDK; TaMin_C: -55°C; ESR_ohm: 2.582m; Polarized: N; SizeAreaWB_mm2: 14.7; Value1: 0.002582 ohm; U/M: EA; Value: 22uF; TaMax_C: 125°C; SizeZ_mm: 2.8; SizeX_mm: 3.2; SizeY_mm: 2.5; Value2: 16V; SizeArea_mm2: 8; AEC Qualified: Y; Cap_F: 22µF; IRMS_A: 4.57562A; AEC Grade: 1; AEC Category: Q200
CN5 = CMP-0079906-1: Connector, Receptacle, Micro-USB Type B, Top Mount SMT; Manufacturer: Hirose Electric Co. Ltd.; Current_A: 1.8A; Gender: Female; Voltage_V: 30V; CompType: USB; ContactFinish: Gold
J1 = CMP-0055471-1: Terminal Block, 5.08 mm, 2x1, TH; Manufacturer: Phoenix Contact; Cert_VDE: Y; CNHeader: FALSE; Current_A: 17.5A; Green_Lifecycle: Not Set; Gender: Female; Cert_CULUS: N; Green_REACh: Incomplete; Voltage_V: 400V; Row_Count: 1; Pitch_mm: 5.08; ContactFinish: Tin; CT: TRUE
J2 J4 J6 J10 J12 J14 = CMP-0075257-1: Header, 2mm, 2x1, Gold, Black, TH; Manufacturer: Harwin; CNHeader: True; Current_A: 1A; Shrouded: N; Gender: Male; Voltage_V: 500V; Row_Count: 1; Pitch_mm: 2; CT: False; Cert_UL: Y
L2 L4-L6 = CMP-0077678-3: Inductor, Shielded, Metal Composite, 470 nH, 3.6 A, 0.032 ohm, SMD; Manufacturer: MuRata; Isat: 4.8A @ 30% inductance drop; Irms: 3.6A @ 40C rise; SizeAreaWB_mm2: 7.8; DCR_ohm: 0.032; Value: 470nH; Imax_A: 3.6A; SizeZ_mm: 1.0; SizeX_mm: 2.0; SizeY_mm: 1.6; SizeArea_mm2: 3.2; AEC Qualified: N; AEC Category: Q200
L3 = CMP-0061150-1: Inductor, Shielded, Composite, 2.2 uH, 3.7 A, 0.02 ohm, SMD; Manufacturer: Coilcraft; Isat: 3.7A @ 30% inductance drop; Irms: 8A @ 40C rise; Green_Lifecycle: Not Set; SizeAreaWB_mm2: 25; DCR_ohm: 0.02; Green_REACh: Incomplete; Value: 2.2uH; Imax_A: 3.7A; SizeZ_mm: 2.15; SizeX_mm: 4; SizeArea_mm2: 16; Ind_H: 2.2µH; AEC Category: Q200
Q1 = CMP-0000092-3: MOSFET, P-CH, -20 V, -3.7 A, SOT-23; Manufacturer: Vishay-Siliconix; Alternate Manufacturer: None; Value: -20V; SizeZ_mm: 1.1; Value2: 12.5 nC; Value1: 0.03; Vgs_V: -8V; IdsMax_A: -3.7A; Rdson45_ohm: 0.031; SizeArea_mm2: 7.5; SizeAreaWB_mm2: 14; ChMode: Enhancement; AEC Category: Q101; SizeX_mm: 2.5; ChType: P; SizeY_mm: 3; QgTyp_nC: 12.5
R4 = CMP-0026993-1: RES, 100, 5%, 0.1 W, AEC-Q200 Grade 0, 0402; Manufacturer: Panasonic; Power_W: 100mW; TempCo: 200 ppm/C; Value_Code: 100R; U/M: EA; Value: 100; EIA_Code: E24; SizeX_mm: 1; SizeY_mm: 0.5; SizeZ_mm: 0.6; Value2: 0.1W; AEC Qualified: Y; AEC Grade: 0; AEC Category: Q200
R13 R129 R131 R170 = CMP-0078779-1: RES, 10.0 k, 1%, 0.2 W, AEC-Q200 Grade 0, 0402; Manufacturer: Panasonic; Value_Code: 10k0; SizeArea_mm2: 0.5; AEC Qualified: Y; AEC Category: Q200; Res_ohm: 10k; Value: 10.0k; SizeZ_mm: 0.6; EIA_Code: E96; TempCo: 100 ppm/C; AEC Grade: 0; Power_W: 200mW; VDC_V: 50V; Value2: 0.2W; SizeX_mm: 1
R41 = CMP-0026822-3: RES, 0, 5%, 0.063 W, AEC-Q200 Grade 0, 0402; PartNumber: CRCW04020000Z0ED; Manufacturer: Vishay-Dale; Value: 0; Value_Code: 0000; Power_W: 63mW; Value2: 0.063W; VDC_V: 50V; TempCo: 200 ppm/C; SizeArea_mm2: 0.5; SizeX_mm: 1; SizeZ_mm: 0.6; EIA_Code: E24; AEC Category: Q200; AEC Qualified: Y
R42 R100 R101 R108 R112 R123 = CMP-0023343-3: RES, 0, 1%, 0.1 W, AEC-Q200 Grade 0, 0603; Manufacturer: Stackpole Electronics Inc; Power_W: 100mW; TempCo: ppm/C; U/M: EA; Value: 0; SizeX_mm: 1.6; SizeY_mm: 0.8; SizeZ_mm: 1; Value2: 0.1W; SizeArea_mm2: 1.28; AEC Qualified: Y; AEC Category: Q200
R87 = CMP-0023343-2: RES, 0, 1%, 0.1 W, AEC-Q200 Grade 0, 0603; Manufacturer: Stackpole Electronics Inc; Power_W: 100mW; TempCo: ppm/C; U/M: EA; Value: 0; SizeX_mm: 1.6; SizeY_mm: 0.8; SizeZ_mm: 1; Value2: 0.1W; SizeArea_mm2: 1.28; AEC Qualified: Y; AEC Category: Q200
R91 R137 R152 = CMP-0019096-2: RES, 100 k, 0.5%, 0.1 W, 0805; Manufacturer: Susumu Co Ltd; Power_W: 100mW; TempCo: 25 ppm/C; U/M: EA; Value: 100k; EIA_Code: E192; SizeX_mm: 2; SizeY_mm: 1.25; SizeZ_mm: 1.45; Value2: 0.1W; SizeArea_mm2: 2.5; VDC_V: 100V; AEC Category: Q200
R92 R102 R103 R145 R146 = CMP-0026635-1: RES, 0.33, 1%, 0.125 W, 0402; Manufacturer: Panasonic; Power_W: 125mW; TempCo: 250 ppm/C; Value_Code: R330; U/M: EA; Value: 0.33; EIA_Code: E96; Res_ohm: 3.3d; SizeX_mm: 1; SizeY_mm: 0.5; SizeZ_mm: 0.6; Value2: 0.125W; AEC Category: Q200
R93 R107 R141 R148 = CMP-0025950-3: RES, 100 k, 1%, 0.063 W, AEC-Q200 Grade 0, 0402; Manufacturer: Vishay-Dale; Power_W: 63mW; TempCo: 100 ppm/C; Value: 100k; EIA_Code: E96; SizeX_mm: 1; SizeY_mm: 0.5; SizeZ_mm: 0.6; Value2: 0.063W; AEC Qualified: Y; VDC_V: 50V; AEC Category: Q200; AEC Grade: 0
R94 = CMP-0026393-2: RES, 475 k, 1%, 0.063 W, AEC-Q200 Grade 0, 0402; Manufacturer: Vishay-Dale; Power_W: 63mW; TempCo: 100 ppm/C; Value: 475k; EIA_Code: E96; SizeX_mm: 1; SizeY_mm: 0.5; SizeZ_mm: 0.6; Value2: 0.063W; AEC Qualified: Y; VDC_V: 50V; AEC Category: Q200; AEC Grade: 0
R99 = CMP-0025986-3: RES, 124 k, 1%, 0.063 W, AEC-Q200 Grade 0, 0402; Manufacturer: Vishay-Dale; Power_W: 63mW; TempCo: 100 ppm/C; Value: 124k; EIA_Code: E96; SizeX_mm: 1; SizeY_mm: 0.5; SizeZ_mm: 0.6; Value2: 0.063W; AEC Qualified: Y; VDC_V: 50V; AEC Category: Q200; AEC Grade: 0
R105 = CMP-0026071-3: RES, 1.00 k, 1%, 0.063 W, AEC-Q200 Grade 0, 0402; Manufacturer: Vishay-Dale; Power_W: 63mW; TempCo: 100 ppm/C; Value_Code: 1k00; Value: 1.00k; EIA_Code: E96; Res_ohm: 1k; SizeX_mm: 1; SizeY_mm: 0.5; SizeZ_mm: 0.6; Value2: 0.063W; AEC Qualified: Y; VDC_V: 50V; AEC Category: Q200; AEC Grade: 0
R109 = CMP-0027754-1: RES, 511 k, 1%, 0.05 W, 0201; Manufacturer: Yageo America; Power_W: 50mW; TempCo: 200 ppm/C; U/M: EA; Value: 511k; EIA_Code: E96; SizeX_mm: 0.6; SizeY_mm: 0.3; SizeZ_mm: 0.26; Value2: 0.05W; SizeArea_mm2: 0.18; AEC Qualified: N; VDC_V: 25V; AEC Category: Q200
R110 = CMP-0023318-5: RES, 91.0 k, 1%, 0.1 W, 0603; Manufacturer: Yageo; Power_W: 100mW; TempCo: 100 ppm/C; Value_Code: 91k0; Value: 91.0k; Res_ohm: 91k; SizeX_mm: 1.6; SizeY_mm: 0.8; SizeZ_mm: 1; Value2: 0.1W; SizeArea_mm2: 1.28; AEC Qualified: N; VDC_V: 75V; AEC Category: Q200; SizeAreaWB_mm2: 4.68
R114 = CMP-0022356-2: RES, 36.5 k, 1%, 0.1 W, 0603; Manufacturer: Vishay-Dale; Power_W: 100mW; TempCo: 100 ppm/C; Value_Code: 36k5; U/M: EA; Value: 36.5k; EIA_Code: E96; SizeX_mm: 1.6; SizeY_mm: 0.8; SizeZ_mm: 1; Value2: 0.1W; SizeArea_mm2: 1.28; VDC_V: 75V; AEC Category: Q200
R116 R118 = CMP-0027293-2: RES, 100 k, 1%, 0.05 W, 0201; Manufacturer: Yageo America; Power_W: 50mW; TempCo: 200 ppm/C; U/M: EA; Value: 100k; EIA_Code: E96; SizeX_mm: 0.6; SizeY_mm: 0.3; SizeZ_mm: 0.26; Value2: 0.05W; SizeArea_mm2: 0.18; AEC Qualified: N; VDC_V: 25V; AEC Category: Q200
R124 R134 R150 = CMP-0023339-3: RES, 0.02, 1%, 0.1 W, AEC-Q200 Grade 0, 0603; Manufacturer: Yageo America; Power_W: 100mW; TempCo: 1500 ppm/C; Value_Code: R020; U/M: EA; Value: 0.02; EIA_Code: E96; SizeX_mm: 1.6; SizeY_mm: 0.8; SizeZ_mm: 1; Value2: 0.1W; SizeArea_mm2: 1.28; AEC Qualified: Y; AEC Grade: 0; AEC Category: Q200
R127 R128 = CMP-0026815-1: RES, 100 k, 0.1%, 0.063 W, 0402; Manufacturer: Susumu Co Ltd; Power_W: 63mW; TempCo: 25 ppm/C; U/M: EA; Value: 100k; EIA_Code: E192; SizeX_mm: 1; SizeY_mm: 0.5; SizeZ_mm: 0.6; Value2: 0.063W; AEC Category: Q200
R135 R149 = CMP-0027891-1: RES, 82.5 k, 1%, 0.05 W, 0201; Manufacturer: Yageo America; Power_W: 50mW; TempCo: 200 ppm/C; Value_Code: 82k5; U/M: EA; Value: 82.5k; EIA_Code: E96; SizeX_mm: 0.6; SizeY_mm: 0.3; SizeZ_mm: 0.26; Value2: 0.05W; SizeArea_mm2: 0.18; AEC Qualified: N; VDC_V: 25V; AEC Category: Q200
R142 = CMP-0026574-2: RES, 82.5 k, 1%, 0.063 W, AEC-Q200 Grade 0, 0402; Manufacturer: Vishay-Dale; Power_W: 63mW; TempCo: 100 ppm/C; Value_Code: 82k5; Value: 82.5k; EIA_Code: E96; SizeX_mm: 1; SizeY_mm: 0.5; SizeZ_mm: 0.6; Value2: 0.063W; AEC Qualified: Y; VDC_V: 50V; AEC Grade: 0; AEC Category: Q200
R147 = CMP-0026158-2: RES, 200 k, 1%, 0.063 W, AEC-Q200 Grade 0, 0402; Manufacturer: Vishay-Dale; Power_W: 63mW; TempCo: 100 ppm/C; Value: 200k; EIA_Code: E96; SizeX_mm: 1; SizeY_mm: 0.5; SizeZ_mm: 0.6; Value2: 0.063W; AEC Qualified: Y; VDC_V: 50V; AEC Category: Q200; AEC Grade: 0
U3 U5 = CMP-0085652-1: +/-6V, Low IQ Ideal Diode with Input Polarity Protection, DCK0006A (SOT-SC70-6); Alternate Manufacturer: Texas Instruments; Alternate PartNumber: LM66100DCKR; SizeArea_mm2: 4.2; AEC Qualified: N; SizeAreaWB_mm2: 9.3; AEC Category: Q200; CompType: IC; SizeZ_mm: 1.1; SizeY_mm: 2; SizeX_mm: 2.1
U4 = CMP-0081107-1: 5.5-V, 1.5-A, 100-mohm Load Switch with Output Discharge, DCK0006A (SOT-SC70-6); Alternate PartNumber: TPS22919DCKR; Alternate Manufacturer: Texas Instruments; SizeAreaWB_mm2: 9.3; SizeZ_mm: 1.1; SizeX_mm: 2.1; SizeY_mm: 2; SizeArea_mm2: 4.2; CompType: IC; AEC Qualified: N; AEC Category: Q200
U7 = CMP-0089990-1: 200-mA, nanopower-IQ (200 nA), low-dropout (LDO) voltage regulator with enable 4-X2SON -40 to 125; Manufacturer: Texas Instruments; Output Type: Fixed; AEC Qualified: No; Max Supply Voltage: 6V; TJmax_C: +125°C; Accuracy Percentage: 1%; Dropout Voltage: 360mV; Nominal Supply Current: 0.2uA; Output Voltage: 2.5V; Standoff Height: 0mm; Number Of Outputs: 1; SizeZ_mm: 0.4mm
U8 = CMP-0043096-2: Low-Capacitance + / - 15 kV ESD-Protection Array for High-Speed Data Interfaces, 2 Channels, -40 to +85 degC, 5-pin SOT (DRL), Green (RoHS & no Sb/Br); Manufacturer: Texas Instruments; IO Leakage Current(nA): 1; IO Capacitance(Typ)(pF): 1.5; USB High Speed: TRUE; SubFamily: ESD Solution; Breakdown Voltage(Min)(V): 11; IEC 61000-4-2 Air-Gap(+/- kV): 15; IEC 61000-4-2 Contact(+/- kV): 8
U11 U16 = CMP-0065148-3: 1A Step-Down Converter With 1% Accuracy, DLC0008A (VSON-HR-8); Manufacturer: Texas Instruments; SizeX_mm: 1.5; SizeY_mm: 2.0; CompType: IC; SizeZ_mm: 1.0; SizeArea_mm2: 3.0; SizeAreaWB_mm2: 7.5; AEC Category: Q200; AEC Qualified: N
U12 = CMP-0076712-5: High Current, High Efficiency Single Inductor Buck-Boost Converter, DLA0010A (VSON-HR-10); Alternate Manufacturer: Texas Instruments; Alternate PartNumber: TPS63802DLAR; SizeAreaWB_mm2: 12.0; SizeY_mm: 3.0; AEC Category: Q200; SizeArea_mm2: 6.0; CompType: IC; AEC Qualified: N; SizeX_mm: 2.0; SizeZ_mm: 1.0
U13 = CMP-0086169-2: TPS63900DSK, DSK0010A (WSON-10); Alternate Manufacturer: Texas Instruments; SizeArea_mm2: 6.25; AEC Category: Q200; SizeX_mm: 2.5; AEC Qualified: N; SizeAreaWB_mm2: 12.25; CompType: IC; SizeZ_mm: 0.8
U14 = CMP-0079420-1: 2-A High Efficiency Synchronous Buck Converter, DMQ0006A (VSON-HR-6); Alternate PartNumber: TPS62825DMQT; Alternate Manufacturer: Texas Instruments; SizeAreaWB_mm2: 6.25; SizeZ_mm: 1; SizeX_mm: 1.5; SizeArea_mm2: 2.25; CompType: IC; AEC Qualified: N; AEC Category: Q200
VBAT = CMP-0067620-1: PC Test Point, SMT; Manufacturer: TE Connectivity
